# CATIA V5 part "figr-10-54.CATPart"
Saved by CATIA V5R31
Part number: Part1
Bounding box of the stored display mesh (mm): x 0 to 100, y -43.492 to 31.433, z -3.653 to 11.537
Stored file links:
  D:\PROJECTS\Project 2021\US EDITION\CATIA V5 6R 2021\Resources\Part Files\c10_catia_v5_6r2021_prt\c10_catia_v5_6r2021_prt\figr-10-54.CATPart
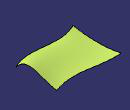
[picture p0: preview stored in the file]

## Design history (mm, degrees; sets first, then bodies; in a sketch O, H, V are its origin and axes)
Set1
  Sketch1 on yz-plane, origin (0, 0, 0), H (0, 1, 0), V (0, 0, 1)
  Plane1: type Offset, RefPlane yz-plane, Offset 100
  Sketch2 on xy-plane, origin (0, 0, 0), H (1, 0, 0), V (0, 1, 0)
    spline S1 through (0, 31.0443) (19.7053, 31.0443) (51.809, 26.4574) (100, 31.0443)
    reference intersected line E1 through (100, 0) direction (0, 1) from Plane1
    point P1 (0, 31.0443)
    point P2 (100, 31.0443)
    coincidence: P1 V, P2 E1
  Sketch3 on xy-plane, origin (0, 0, 0), H (1, 0, 0), V (0, 1, 0)
    spline S1 through (0, -43.492) (26.209, -36.2295) (80.3728, -38.1407) (100, -32.0249)
    reference intersected line E1 through (100, 0) direction (0, 1) from Plane1
    point P1 (0, -43.492)
    point P2 (100, -32.0249)
    coincidence: P1 V, P2 E1
  Sketch4 on Plane1, origin (100, 0, 0), H (0, 1, 0), V (0, 0, 1)
    spline S1 through (-32.0249, 0) (-14.5305, 11.3827) (11.9668, 5.3652) (31.0443, 0)
    reference projected point E1 (31.0443, 0) from vertex of Sketch2
    reference projected point E2 (-32.0249, 0) from vertex of Sketch3
    point P1 (-32.0249, 0)
    point P2 (31.0443, 0)
    coincidence: P1 H, P2 H, P2 E1, P1 E2
  Sketch5 on yz-plane, origin (0, 0, 0), H (0, 1, 0), V (0, 0, 1)
    spline S1 through (31.0443, 0) (7.4727, -3.1675) (-43.492, 0)
    reference projected point E1 (-43.492, 0) from vertex of Sketch3
    reference projected point E2 (31.0443, 0) from vertex of Sketch2
    point P1 (31.0443, 0)
    point P2 (-43.492, 0)
    coincidence: P1 H, P2 H, P2 E1, P1 E2
  Fill1: Boundary (Sketch5; Sketch3; Sketch4; Sketch2)
Body1 (main body)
